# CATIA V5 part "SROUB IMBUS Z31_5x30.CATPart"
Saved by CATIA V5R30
Part number: SROUB IMBUS Z31/5x30
Bounding box of the stored display mesh (mm): x -5 to 30, y -4.24 to 4.24, z -4.25 to 4.25
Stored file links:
  C:\Users\ondra\Desktop\PŘÍLOHA P III\CATIA\SROUB IMBUS Z31_5x30.CATPart
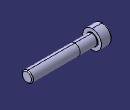
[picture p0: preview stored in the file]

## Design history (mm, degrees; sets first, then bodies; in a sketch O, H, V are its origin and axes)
Set1
  DatumSurface1 to DatumSurface29 "Z31/5x30"
  Join1: Elements (DatumSurface1; DatumSurface2; DatumSurface3; DatumSurface4; DatumSurface5; DatumSurface6; DatumSurface7; DatumSurface8; DatumSurface9; DatumSurface10; DatumSurface11; DatumSurface12; DatumSurface13; DatumSurface14; DatumSurface15; DatumSurface16; DatumSurface17; DatumSurface18; DatumSurface19; DatumSurface20; DatumSurface21; DatumSurface22; DatumSurface23; DatumSurface24; DatumSurface25; DatumSurface26; DatumSurface27; DatumSurface28; DatumSurface29)
Set2 "Geometry Failure"
  Set3 "FaceKO#Z31/5x30#409"
    DatumSurface30 "Sur409_1"
    Circle1 "Crv409_1": stored without definition
    DatumCurve1 "PCrv409_1"
    Circle2 "Crv409_2": stored without definition
    DatumCurve2 "PCrv409_2"
    Circle3 "Crv409_3": stored without definition
    DatumCurve3 "PCrv409_3"
    Circle4 "Crv409_4": stored without definition
    DatumCurve4 "PCrv409_4"
Body1 (main body)
  CloseSurface1: CloseElement Join1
